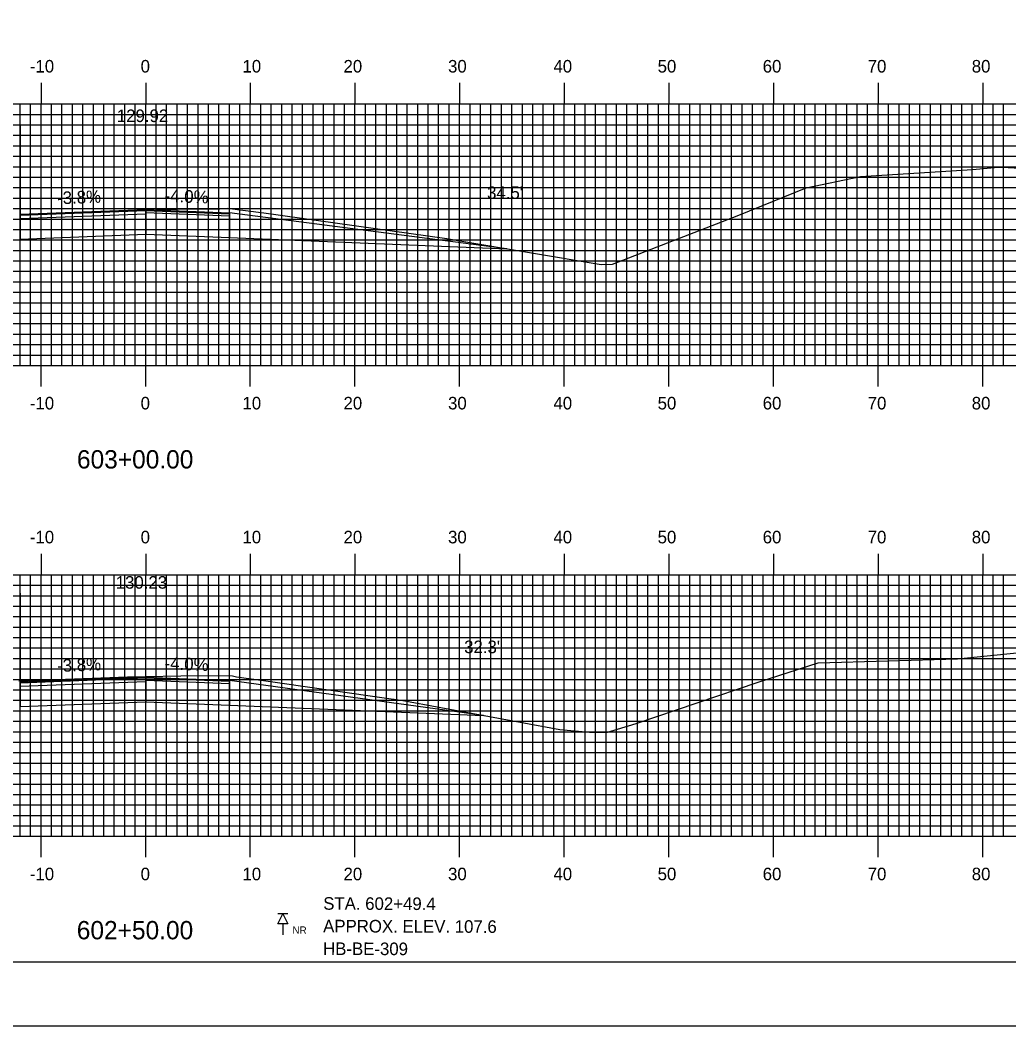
# Model space of a CAD drawing. Extents: x 841782 to 842125, y 363538 to 363758.
# Drawn here: x 841935.4 to 842029.9, y 363537.6 to 363633.7 of the extents above; entities that cross this region are included whole.
import ezdxf

# ---------------------------------------------------------------- set-up
doc = ezdxf.new("R2010")
doc.units = 0
for name, color, linetype in [('ANNOTATION', 7, 'Continuous'), ('BORDER', 7, 'Continuous'), ('BORING - NO REFUSAL', 7, 'Continuous'), ('D_Roadway_Centerline', 7, 'Continuous'), ('D_Roadway_Centerline_Text', 7, 'Continuous'), ('D_Roadway_Edge_Shoulder', 7, 'Continuous'), ('D_Roadway_Edge_TW', 7, 'Continuous'), ('D_Roadway_SubGrade', 7, 'Continuous'), ('D_Text_Standard', 7, 'Continuous'), ('H_V ANNOTATION', 7, 'Continuous'), ('MAJOR', 7, 'Continuous'), ('MINOR', 7, 'Continuous'), ('PLOT BOUNDARY', 7, 'Continuous'), ('S_Roadway_Centerline', 7, 'Continuous')]:
    doc.layers.add(name, color=color, linetype=linetype)

msp = doc.modelspace()

# ---------------------------------------------------------------- linework, layer by layer
at = {"layer": 'ANNOTATION'}
for p, q in [((841947.372, 363615.514), (841947.372, 363613.264)), ((841935.372, 363615.058), (841935.372, 363612.808)), ((841955.372, 363615.194), (841955.372, 363612.944)), ((841935.372, 363570.366), (841935.372, 363568.116)), ((841947.372, 363570.822), (841947.372, 363568.572)), ((841955.372, 363570.502), (841955.372, 363568.252))]:
    msp.add_line(p, q, dxfattribs=at)
at = {"layer": 'BORDER'}
msp.add_lwpolyline([(841797.772, 363543.721), (842117.772, 363543.721), (842117.772, 363753.721), (841797.772, 363753.721)], close=True, dxfattribs=at)
at = {"layer": 'BORING - NO REFUSAL'}
for p, q in [((841960.952, 363548.321), (841959.992, 363548.321)), ((841960.472, 363547.361), (841960.472, 363546.302))]:
    msp.add_line(p, q, dxfattribs=at)
msp.add_lwpolyline([(841960.472, 363548.321), (841960.952, 363547.361), (841959.992, 363547.361)], close=True, dxfattribs=at)
at = {"layer": 'D_Roadway_Centerline'}
for points in [[(841935.372, 363615.183), (841947.372, 363615.639), (841955.372, 363615.319)], [(841935.372, 363570.491), (841947.372, 363570.947), (841955.372, 363570.627)]]:
    msp.add_lwpolyline(points, dxfattribs=at)
at = {"layer": 'D_Roadway_Edge_Shoulder'}
for points in [[(841947.372, 363615.639), (841955.372, 363615.319), (841955.372, 363615.194), (841947.372, 363615.514)], [(841947.372, 363570.947), (841955.372, 363570.627), (841955.372, 363570.502), (841947.372, 363570.822)]]:
    msp.add_lwpolyline(points, close=True, dxfattribs=at)
at = {"layer": 'D_Roadway_Edge_TW'}
for points in [[(841935.372, 363615.183), (841947.372, 363615.639), (841947.372, 363615.514), (841935.372, 363615.058)], [(841935.372, 363570.491), (841947.372, 363570.947), (841947.372, 363570.822), (841935.372, 363570.366)]]:
    msp.add_lwpolyline(points, close=True, dxfattribs=at)
for points in [[(841935.372, 363615.183), (841935.372, 363615.058)], [(841935.372, 363570.491), (841935.372, 363570.366)]]:
    msp.add_lwpolyline(points, dxfattribs=at)
at = {"layer": 'D_Roadway_SubGrade'}
for p, q in [((841935.372, 363623.656), (841935.372, 363615.058)), ((841947.372, 363615.514), (841947.372, 363613.264)), ((841935.372, 363612.808), (841935.372, 363615.058)), ((841935.372, 363578.963), (841935.372, 363570.366)), ((841935.372, 363568.116), (841935.372, 363570.366)), ((841947.372, 363570.822), (841947.372, 363568.572))]:
    msp.add_line(p, q, dxfattribs=at)
for points in [[(841947.372, 363615.514), (841947.372, 363615.181), (841935.372, 363614.725)], [(841947.372, 363615.514), (841947.372, 363615.347), (841955.372, 363615.027)], [(841935.372, 363615.058), (841935.372, 363612.808), (841947.372, 363613.264), (841955.372, 363612.944), (841955.372, 363615.194)], [(841955.372, 363612.944), (841981.88, 363611.884), (841955.372, 363615.319)], [(841947.372, 363570.822), (841947.372, 363570.489), (841935.372, 363570.033)], [(841935.372, 363570.366), (841935.372, 363568.116), (841947.372, 363568.572), (841955.372, 363568.252), (841955.372, 363570.502)], [(841947.372, 363570.822), (841947.372, 363570.655), (841955.372, 363570.335)], [(841955.372, 363568.252), (841979.649, 363567.281), (841955.372, 363570.627)]]:
    msp.add_lwpolyline(points, dxfattribs=at)
at = {"layer": 'MAJOR'}
for p, q in [((841937.372, 363627.725), (841937.372, 363625.721)), ((841947.372, 363627.725), (841947.372, 363625.721)), ((841957.372, 363627.725), (841957.372, 363625.721)), ((841967.372, 363627.725), (841967.372, 363625.721)), ((841977.372, 363627.725), (841977.372, 363625.721)), ((841987.372, 363627.725), (841987.372, 363625.721)), ((841997.372, 363627.725), (841997.372, 363625.721)), ((842007.372, 363627.725), (842007.372, 363625.721)), ((842017.372, 363627.725), (842017.372, 363625.721)), ((842027.372, 363627.725), (842027.372, 363625.721)), ((841807.372, 363625.721), (842087.372, 363625.721)), ((841807.372, 363625.721), (842087.372, 363625.721)), ((841937.372, 363600.721), (841937.372, 363625.721)), ((841947.372, 363600.721), (841947.372, 363625.721)), ((841957.372, 363600.721), (841957.372, 363625.721)), ((841967.372, 363600.721), (841967.372, 363625.721)), ((841977.372, 363600.721), (841977.372, 363625.721)), ((841987.372, 363600.721), (841987.372, 363625.721)), ((841997.372, 363600.721), (841997.372, 363625.721)), ((842007.372, 363600.721), (842007.372, 363625.721)), ((842017.372, 363600.721), (842017.372, 363625.721)), ((842027.372, 363600.721), (842027.372, 363625.721)), ((841807.372, 363620.721), (842087.372, 363620.721)), ((841807.372, 363615.721), (842087.372, 363615.721)), ((841807.372, 363610.721), (842087.372, 363610.721)), ((841807.372, 363605.721), (842087.372, 363605.721)), ((841807.372, 363600.721), (842087.372, 363600.721)), ((841807.372, 363600.721), (842087.372, 363600.721)), ((841937.372, 363598.717), (841937.372, 363600.721)), ((841947.372, 363598.717), (841947.372, 363600.721)), ((841957.372, 363598.717), (841957.372, 363600.721)), ((841967.372, 363598.717), (841967.372, 363600.721)), ((841977.372, 363598.717), (841977.372, 363600.721)), ((841987.372, 363598.717), (841987.372, 363600.721)), ((841997.372, 363598.717), (841997.372, 363600.721)), ((842007.372, 363598.717), (842007.372, 363600.721)), ((842017.372, 363598.717), (842017.372, 363600.721)), ((842027.372, 363598.717), (842027.372, 363600.721)), ((841937.372, 363582.725), (841937.372, 363580.721)), ((841947.372, 363582.725), (841947.372, 363580.721)), ((841957.372, 363582.725), (841957.372, 363580.721)), ((841967.372, 363582.725), (841967.372, 363580.721)), ((841977.372, 363582.725), (841977.372, 363580.721)), ((841987.372, 363582.725), (841987.372, 363580.721)), ((841997.372, 363582.725), (841997.372, 363580.721)), ((842007.372, 363582.725), (842007.372, 363580.721)), ((842017.372, 363582.725), (842017.372, 363580.721)), ((842027.372, 363582.725), (842027.372, 363580.721)), ((841807.372, 363580.721), (842087.372, 363580.721)), ((841807.372, 363580.721), (842087.372, 363580.721)), ((841937.372, 363555.721), (841937.372, 363580.721)), ((841947.372, 363555.721), (841947.372, 363580.721)), ((841957.372, 363555.721), (841957.372, 363580.721)), ((841967.372, 363555.721), (841967.372, 363580.721)), ((841977.372, 363555.721), (841977.372, 363580.721)), ((841987.372, 363555.721), (841987.372, 363580.721)), ((841997.372, 363555.721), (841997.372, 363580.721)), ((842007.372, 363555.721), (842007.372, 363580.721)), ((842017.372, 363555.721), (842017.372, 363580.721)), ((842027.372, 363555.721), (842027.372, 363580.721)), ((841807.372, 363575.721), (842087.372, 363575.721)), ((841807.372, 363570.721), (842087.372, 363570.721)), ((841807.372, 363565.721), (842087.372, 363565.721)), ((841807.372, 363560.721), (842087.372, 363560.721)), ((841807.372, 363555.721), (842087.372, 363555.721)), ((841807.372, 363555.721), (842087.372, 363555.721)), ((841937.372, 363553.717), (841937.372, 363555.721)), ((841947.372, 363553.717), (841947.372, 363555.721)), ((841957.372, 363553.717), (841957.372, 363555.721)), ((841967.372, 363553.717), (841967.372, 363555.721)), ((841977.372, 363553.717), (841977.372, 363555.721)), ((841987.372, 363553.717), (841987.372, 363555.721)), ((841997.372, 363553.717), (841997.372, 363555.721)), ((842007.372, 363553.717), (842007.372, 363555.721)), ((842017.372, 363553.717), (842017.372, 363555.721)), ((842027.372, 363553.717), (842027.372, 363555.721))]:
    msp.add_line(p, q, dxfattribs=at)
at = {"layer": 'MINOR'}
for p, q in [((841935.372, 363600.721), (841935.372, 363625.721)), ((841936.372, 363600.721), (841936.372, 363625.721)), ((841938.372, 363600.721), (841938.372, 363625.721)), ((841939.372, 363600.721), (841939.372, 363625.721)), ((841940.372, 363600.721), (841940.372, 363625.721)), ((841941.372, 363600.721), (841941.372, 363625.721)), ((841942.372, 363600.721), (841942.372, 363625.721)), ((841943.372, 363600.721), (841943.372, 363625.721)), ((841944.372, 363600.721), (841944.372, 363625.721)), ((841945.372, 363600.721), (841945.372, 363625.721)), ((841946.372, 363600.721), (841946.372, 363625.721)), ((841948.372, 363600.721), (841948.372, 363625.721)), ((841949.372, 363600.721), (841949.372, 363625.721)), ((841950.372, 363600.721), (841950.372, 363625.721)), ((841951.372, 363600.721), (841951.372, 363625.721)), ((841952.372, 363600.721), (841952.372, 363625.721)), ((841953.372, 363600.721), (841953.372, 363625.721)), ((841954.372, 363600.721), (841954.372, 363625.721)), ((841955.372, 363600.721), (841955.372, 363625.721)), ((841956.372, 363600.721), (841956.372, 363625.721)), ((841958.372, 363600.721), (841958.372, 363625.721)), ((841959.372, 363600.721), (841959.372, 363625.721)), ((841960.372, 363600.721), (841960.372, 363625.721)), ((841961.372, 363600.721), (841961.372, 363625.721)), ((841962.372, 363600.721), (841962.372, 363625.721)), ((841963.372, 363600.721), (841963.372, 363625.721)), ((841964.372, 363600.721), (841964.372, 363625.721)), ((841965.372, 363600.721), (841965.372, 363625.721)), ((841966.372, 363600.721), (841966.372, 363625.721)), ((841968.372, 363600.721), (841968.372, 363625.721)), ((841969.372, 363600.721), (841969.372, 363625.721)), ((841970.372, 363600.721), (841970.372, 363625.721)), ((841971.372, 363600.721), (841971.372, 363625.721)), ((841972.372, 363600.721), (841972.372, 363625.721)), ((841973.372, 363600.721), (841973.372, 363625.721)), ((841974.372, 363600.721), (841974.372, 363625.721)), ((841975.372, 363600.721), (841975.372, 363625.721)), ((841976.372, 363600.721), (841976.372, 363625.721)), ((841978.372, 363600.721), (841978.372, 363625.721)), ((841979.372, 363600.721), (841979.372, 363625.721)), ((841980.372, 363600.721), (841980.372, 363625.721)), ((841981.372, 363600.721), (841981.372, 363625.721)), ((841982.372, 363600.721), (841982.372, 363625.721)), ((841983.372, 363600.721), (841983.372, 363625.721)), ((841984.372, 363600.721), (841984.372, 363625.721)), ((841985.372, 363600.721), (841985.372, 363625.721)), ((841986.372, 363600.721), (841986.372, 363625.721)), ((841988.372, 363600.721), (841988.372, 363625.721)), ((841989.372, 363600.721), (841989.372, 363625.721)), ((841990.372, 363600.721), (841990.372, 363625.721)), ((841991.372, 363600.721), (841991.372, 363625.721)), ((841992.372, 363600.721), (841992.372, 363625.721)), ((841993.372, 363600.721), (841993.372, 363625.721)), ((841994.372, 363600.721), (841994.372, 363625.721)), ((841995.372, 363600.721), (841995.372, 363625.721)), ((841996.372, 363600.721), (841996.372, 363625.721)), ((841998.372, 363600.721), (841998.372, 363625.721)), ((841999.372, 363600.721), (841999.372, 363625.721)), ((842000.372, 363600.721), (842000.372, 363625.721)), ((842001.372, 363600.721), (842001.372, 363625.721)), ((842002.372, 363600.721), (842002.372, 363625.721)), ((842003.372, 363600.721), (842003.372, 363625.721)), ((842004.372, 363600.721), (842004.372, 363625.721)), ((842005.372, 363600.721), (842005.372, 363625.721)), ((842006.372, 363600.721), (842006.372, 363625.721)), ((842008.372, 363600.721), (842008.372, 363625.721)), ((842009.372, 363600.721), (842009.372, 363625.721)), ((842010.372, 363600.721), (842010.372, 363625.721)), ((842011.372, 363600.721), (842011.372, 363625.721)), ((842012.372, 363600.721), (842012.372, 363625.721)), ((842013.372, 363600.721), (842013.372, 363625.721)), ((842014.372, 363600.721), (842014.372, 363625.721)), ((842015.372, 363600.721), (842015.372, 363625.721)), ((842016.372, 363600.721), (842016.372, 363625.721)), ((842018.372, 363600.721), (842018.372, 363625.721)), ((842019.372, 363600.721), (842019.372, 363625.721)), ((842020.372, 363600.721), (842020.372, 363625.721)), ((842021.372, 363600.721), (842021.372, 363625.721)), ((842022.372, 363600.721), (842022.372, 363625.721)), ((842023.372, 363600.721), (842023.372, 363625.721)), ((842024.372, 363600.721), (842024.372, 363625.721)), ((842025.372, 363600.721), (842025.372, 363625.721)), ((842026.372, 363600.721), (842026.372, 363625.721)), ((842028.372, 363600.721), (842028.372, 363625.721)), ((842029.372, 363600.721), (842029.372, 363625.721)), ((841807.372, 363624.721), (842087.372, 363624.721)), ((841807.372, 363623.721), (842087.372, 363623.721)), ((841807.372, 363622.721), (842087.372, 363622.721)), ((841807.372, 363621.721), (842087.372, 363621.721)), ((841807.372, 363619.721), (842087.372, 363619.721)), ((841807.372, 363618.721), (842087.372, 363618.721)), ((841807.372, 363617.721), (842087.372, 363617.721)), ((841807.372, 363616.721), (842087.372, 363616.721)), ((841807.372, 363614.721), (842087.372, 363614.721)), ((841807.372, 363613.721), (842087.372, 363613.721)), ((841807.372, 363612.721), (842087.372, 363612.721)), ((841807.372, 363611.721), (842087.372, 363611.721)), ((841807.372, 363609.721), (842087.372, 363609.721)), ((841807.372, 363608.721), (842087.372, 363608.721)), ((841807.372, 363607.721), (842087.372, 363607.721)), ((841807.372, 363606.721), (842087.372, 363606.721)), ((841807.372, 363604.721), (842087.372, 363604.721)), ((841807.372, 363603.721), (842087.372, 363603.721)), ((841807.372, 363602.721), (842087.372, 363602.721)), ((841807.372, 363601.721), (842087.372, 363601.721)), ((841935.372, 363555.721), (841935.372, 363580.721)), ((841936.372, 363555.721), (841936.372, 363580.721)), ((841938.372, 363555.721), (841938.372, 363580.721)), ((841939.372, 363555.721), (841939.372, 363580.721)), ((841940.372, 363555.721), (841940.372, 363580.721)), ((841941.372, 363555.721), (841941.372, 363580.721)), ((841942.372, 363555.721), (841942.372, 363580.721)), ((841943.372, 363555.721), (841943.372, 363580.721)), ((841944.372, 363555.721), (841944.372, 363580.721)), ((841945.372, 363555.721), (841945.372, 363580.721)), ((841946.372, 363555.721), (841946.372, 363580.721)), ((841948.372, 363555.721), (841948.372, 363580.721)), ((841949.372, 363555.721), (841949.372, 363580.721)), ((841950.372, 363555.721), (841950.372, 363580.721)), ((841951.372, 363555.721), (841951.372, 363580.721)), ((841952.372, 363555.721), (841952.372, 363580.721)), ((841953.372, 363555.721), (841953.372, 363580.721)), ((841954.372, 363555.721), (841954.372, 363580.721)), ((841955.372, 363555.721), (841955.372, 363580.721)), ((841956.372, 363555.721), (841956.372, 363580.721)), ((841958.372, 363555.721), (841958.372, 363580.721)), ((841959.372, 363555.721), (841959.372, 363580.721)), ((841960.372, 363555.721), (841960.372, 363580.721)), ((841961.372, 363555.721), (841961.372, 363580.721)), ((841962.372, 363555.721), (841962.372, 363580.721)), ((841963.372, 363555.721), (841963.372, 363580.721)), ((841964.372, 363555.721), (841964.372, 363580.721)), ((841965.372, 363555.721), (841965.372, 363580.721)), ((841966.372, 363555.721), (841966.372, 363580.721)), ((841968.372, 363555.721), (841968.372, 363580.721)), ((841969.372, 363555.721), (841969.372, 363580.721)), ((841970.372, 363555.721), (841970.372, 363580.721)), ((841971.372, 363555.721), (841971.372, 363580.721)), ((841972.372, 363555.721), (841972.372, 363580.721)), ((841973.372, 363555.721), (841973.372, 363580.721)), ((841974.372, 363555.721), (841974.372, 363580.721)), ((841975.372, 363555.721), (841975.372, 363580.721)), ((841976.372, 363555.721), (841976.372, 363580.721)), ((841978.372, 363555.721), (841978.372, 363580.721)), ((841979.372, 363555.721), (841979.372, 363580.721)), ((841980.372, 363555.721), (841980.372, 363580.721)), ((841981.372, 363555.721), (841981.372, 363580.721)), ((841982.372, 363555.721), (841982.372, 363580.721)), ((841983.372, 363555.721), (841983.372, 363580.721)), ((841984.372, 363555.721), (841984.372, 363580.721)), ((841985.372, 363555.721), (841985.372, 363580.721)), ((841986.372, 363555.721), (841986.372, 363580.721)), ((841988.372, 363555.721), (841988.372, 363580.721)), ((841989.372, 363555.721), (841989.372, 363580.721)), ((841990.372, 363555.721), (841990.372, 363580.721)), ((841991.372, 363555.721), (841991.372, 363580.721)), ((841992.372, 363555.721), (841992.372, 363580.721)), ((841993.372, 363555.721), (841993.372, 363580.721)), ((841994.372, 363555.721), (841994.372, 363580.721)), ((841995.372, 363555.721), (841995.372, 363580.721)), ((841996.372, 363555.721), (841996.372, 363580.721)), ((841998.372, 363555.721), (841998.372, 363580.721)), ((841999.372, 363555.721), (841999.372, 363580.721)), ((842000.372, 363555.721), (842000.372, 363580.721)), ((842001.372, 363555.721), (842001.372, 363580.721)), ((842002.372, 363555.721), (842002.372, 363580.721)), ((842003.372, 363555.721), (842003.372, 363580.721)), ((842004.372, 363555.721), (842004.372, 363580.721)), ((842005.372, 363555.721), (842005.372, 363580.721)), ((842006.372, 363555.721), (842006.372, 363580.721)), ((842008.372, 363555.721), (842008.372, 363580.721)), ((842009.372, 363555.721), (842009.372, 363580.721)), ((842010.372, 363555.721), (842010.372, 363580.721)), ((842011.372, 363555.721), (842011.372, 363580.721)), ((842012.372, 363555.721), (842012.372, 363580.721)), ((842013.372, 363555.721), (842013.372, 363580.721)), ((842014.372, 363555.721), (842014.372, 363580.721)), ((842015.372, 363555.721), (842015.372, 363580.721)), ((842016.372, 363555.721), (842016.372, 363580.721)), ((842018.372, 363555.721), (842018.372, 363580.721)), ((842019.372, 363555.721), (842019.372, 363580.721)), ((842020.372, 363555.721), (842020.372, 363580.721)), ((842021.372, 363555.721), (842021.372, 363580.721)), ((842022.372, 363555.721), (842022.372, 363580.721)), ((842023.372, 363555.721), (842023.372, 363580.721)), ((842024.372, 363555.721), (842024.372, 363580.721)), ((842025.372, 363555.721), (842025.372, 363580.721)), ((842026.372, 363555.721), (842026.372, 363580.721)), ((842028.372, 363555.721), (842028.372, 363580.721)), ((842029.372, 363555.721), (842029.372, 363580.721)), ((841807.372, 363579.721), (842087.372, 363579.721)), ((841807.372, 363578.721), (842087.372, 363578.721)), ((841807.372, 363577.721), (842087.372, 363577.721)), ((841807.372, 363576.721), (842087.372, 363576.721)), ((841807.372, 363574.721), (842087.372, 363574.721)), ((841807.372, 363573.721), (842087.372, 363573.721)), ((841807.372, 363572.721), (842087.372, 363572.721)), ((841807.372, 363571.721), (842087.372, 363571.721)), ((841807.372, 363569.721), (842087.372, 363569.721)), ((841807.372, 363568.721), (842087.372, 363568.721)), ((841807.372, 363567.721), (842087.372, 363567.721)), ((841807.372, 363566.721), (842087.372, 363566.721)), ((841807.372, 363564.721), (842087.372, 363564.721)), ((841807.372, 363563.721), (842087.372, 363563.721)), ((841807.372, 363562.721), (842087.372, 363562.721)), ((841807.372, 363561.721), (842087.372, 363561.721)), ((841807.372, 363559.721), (842087.372, 363559.721)), ((841807.372, 363558.721), (842087.372, 363558.721)), ((841807.372, 363557.721), (842087.372, 363557.721)), ((841807.372, 363556.721), (842087.372, 363556.721))]:
    msp.add_line(p, q, dxfattribs=at)
at = {"layer": 'PLOT BOUNDARY'}
msp.add_lwpolyline([(841781.585, 363537.603), (842121.585, 363537.603), (842121.585, 363757.603), (841781.585, 363757.603)], close=True, dxfattribs=at)
at = {"layer": 'S_Roadway_Centerline'}
for points in [[(841935.358, 363615.194), (841938.117, 363615.234), (841938.822, 363615.265), (841951.305, 363615.687), (841954.445, 363615.699), (841955.175, 363615.744), (841958.675, 363615.3), (841963.903, 363614.586), (841976.148, 363612.85), (841977.39, 363612.639), (841990.914, 363610.364), (841991.988, 363610.403), (842004.055, 363615.079), (842010.509, 363617.704), (842015.685, 363618.798), (842026.394, 363619.448), (842028.855, 363619.68), (842029.789, 363619.65), (842042.082, 363618.964), (842048.29, 363618.678), (842054.647, 363618.429), (842067.042, 363618.102), (842083.57, 363617.344), (842087.372, 363617.004)], [(841935.262, 363570.58), (841938.032, 363570.662), (841945.624, 363570.969), (841952.416, 363571.1), (841955.684, 363571.055), (841956.058, 363570.954), (841958.622, 363570.61), (841970.84, 363568.868), (841971.116, 363568.832), (841971.495, 363568.776), (841971.775, 363568.73), (841986.967, 363565.933), (841989.783, 363565.667), (841991.422, 363565.656), (841994.256, 363566.502), (842005.9, 363570.467), (842011.644, 363572.312), (842024.963, 363572.671), (842033.778, 363573.589)]]:
    msp.add_lwpolyline(points, dxfattribs=at)

# ---------------------------------------------------------------- texts
at = {"layer": 'ANNOTATION'}
for s, rotation, p in [('-3.8%', 2.17619, (841938.933, 363616.12)), ('-4.0%', 357.70939, (841949.164, 363616.369)), ('-3.8%', 2.17619, (841938.933, 363571.428)), ('-4.0%', 357.70939, (841949.164, 363571.677))]:
    msp.add_text(s, height=1.2, rotation=rotation, dxfattribs=at).set_placement(p)
at = {"layer": 'BORING - NO REFUSAL'}
for s, p in [('STA. 602+49.4', (841964.339, 363548.706)), ('APPROX. ELEV. 107.6', (841964.332, 363546.546)), ('HB-BE-309', (841964.325, 363544.386))]:
    msp.add_text(s, height=1.2, rotation=359.81416, dxfattribs=at).set_placement(p)
msp.add_text('NR', height=0.6998, dxfattribs=at).set_placement((841961.405, 363546.406))
at = {"layer": 'D_Roadway_Centerline_Text'}
for s, p in [('129.92', (841944.616, 363623.985)), ('130.23', (841944.509, 363579.388))]:
    msp.add_text(s, height=1.2, dxfattribs=at).set_placement(p)
at = {"layer": 'D_Text_Standard'}
for s, p in [("34.5'", (841980.003, 363616.638)), ("32.3'", (841977.811, 363573.227))]:
    msp.add_text(s, height=1.2, dxfattribs=at).set_placement(p)
at = {"layer": 'H_V ANNOTATION'}
for s, height, p in [('-10', 1.2, (841936.302, 363628.721)), ('0', 1.2, (841946.89, 363628.721)), ('10', 1.2, (841956.623, 363628.721)), ('20', 1.2, (841966.28, 363628.721)), ('30', 1.2, (841976.269, 363628.721)), ('40', 1.2, (841986.344, 363628.721)), ('50', 1.2, (841996.301, 363628.721)), ('60', 1.2, (842006.344, 363628.721)), ('70', 1.2, (842016.376, 363628.721)), ('80', 1.2, (842026.323, 363628.721)), ('-10', 1.2, (841936.302, 363596.521)), ('0', 1.2, (841946.89, 363596.521)), ('10', 1.2, (841956.623, 363596.521)), ('20', 1.2, (841966.28, 363596.521)), ('30', 1.2, (841976.269, 363596.521)), ('40', 1.2, (841986.344, 363596.521)), ('50', 1.2, (841996.301, 363596.521)), ('60', 1.2, (842006.344, 363596.521)), ('70', 1.2, (842016.376, 363596.521)), ('80', 1.2, (842026.323, 363596.521)), ('603+00.00', 1.75, (841940.802, 363590.877)), ('-10', 1.2, (841936.302, 363583.721)), ('0', 1.2, (841946.89, 363583.721)), ('10', 1.2, (841956.623, 363583.721)), ('20', 1.2, (841966.28, 363583.721)), ('30', 1.2, (841976.269, 363583.721)), ('40', 1.2, (841986.344, 363583.721)), ('50', 1.2, (841996.301, 363583.721)), ('60', 1.2, (842006.344, 363583.721)), ('70', 1.2, (842016.376, 363583.721)), ('80', 1.2, (842026.323, 363583.721)), ('-10', 1.2, (841936.302, 363551.521)), ('0', 1.2, (841946.89, 363551.521)), ('10', 1.2, (841956.623, 363551.521)), ('20', 1.2, (841966.28, 363551.521)), ('30', 1.2, (841976.269, 363551.521)), ('40', 1.2, (841986.344, 363551.521)), ('50', 1.2, (841996.301, 363551.521)), ('60', 1.2, (842006.344, 363551.521)), ('70', 1.2, (842016.376, 363551.521)), ('80', 1.2, (842026.323, 363551.521)), ('602+50.00', 1.75, (841940.786, 363545.877))]:
    msp.add_text(s, height=height, dxfattribs=at).set_placement(p)

doc.saveas('drawing.dxf')
